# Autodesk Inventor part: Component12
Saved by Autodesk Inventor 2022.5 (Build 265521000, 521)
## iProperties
Created: 2024-12
Part Number: Component12
Material: Generic
Document SubType Name: Modeling
Designer: AdminForWorker
Density: 1 g/cm^3
Appearance: Default
Title: Component12
Author: AdminForWorker
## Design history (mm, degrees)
feature "Body2"
body "Solid1"
